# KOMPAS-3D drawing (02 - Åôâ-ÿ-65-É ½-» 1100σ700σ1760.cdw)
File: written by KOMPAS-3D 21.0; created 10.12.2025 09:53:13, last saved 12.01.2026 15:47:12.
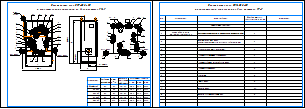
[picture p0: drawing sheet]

Sheets 1-2: A3, landscape

Document properties: Автор: RaskoAdmin; Форматы листов документа: 2xA3; Полное имя файла: \\ur38nt01\Departments\КТО\КБ ПУРДГ\Заявки\Прайс-лист на типовые шкафы ГРПШ\ПУГ-Ш-65-Р л-п 1100х700х1760.cdw

Title block, sheet 1: sheet number: 1; Количество листов документа: 2; Форматы листов документа: A3; stored path: \\ur38nt01\Departments\КТО\КБ ПУРДГ\Заявки\Прайс-лист на типовые шкафы ГРПШ\ПУГ-ШУЭО-65-Р л-п.cdw
Title block, sheet 2: sheet number: 2

Views: Вид 1
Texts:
  Вход Ду50
  Выход Ду50
  Пункт учета газа ПУГ-Ш Ду50
  с измерительным комплексом на базе счетчика РГ-Р
  Условный
  проход Ду, мм
  Qmax,
  Диапазон
  измерений
  Qmin/Qmax
  Габаритные размеры
  А, мм
  В, мм
  Н, мм
  ПУГ-Ш-16-Р
  Поз.
  Условный проход
  расходомера Ду 50, мм
  СГ-ЭК-Р-(0,2...2,0)-
  Стандартные изделия
  Измерительный комплекс с ротационным счетчиком Ду50
  Фильтр газа ФГ Ду50
  (Оснащен индикатором перепада давления ДПД)
  Кран кнопочный под манометр
  Кран шаровой штуцерный Ду20
  Кран шаровый с мех.приводом Ду50
  Кран шаровый Ду50
  Манометр
  Отвод Ду50
  Фланец Ду50
  Фланец воротниковый Ду50
  Ду20
  Свеча
  POLYLINE_STYLE_0.18_RGB_0_0_0
  Без основной надписи.
Dimensions and other numbers on the sheet: 550±80; 1; 2; 3; 4; 5; 6; 7; 8; 9; 10; -40-Р; -25-Р; -65-Р; -100-Р; 50; 40; 25; 16; 65; 100; 0,5/40; 0,5/25; 0,3/16; 0,5/65; 0,4/100; 1100; 700; 1760; 1:15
